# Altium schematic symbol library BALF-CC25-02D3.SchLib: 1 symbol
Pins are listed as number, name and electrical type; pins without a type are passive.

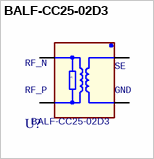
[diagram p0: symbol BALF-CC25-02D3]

## BALF-CC25-02D3
designator U?
footprint ST_CSP04N50P2X2_94X94X63
pins: A1 SE, A2 RF_N, B1 GND, B2 RF_P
